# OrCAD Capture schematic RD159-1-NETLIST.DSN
size A3
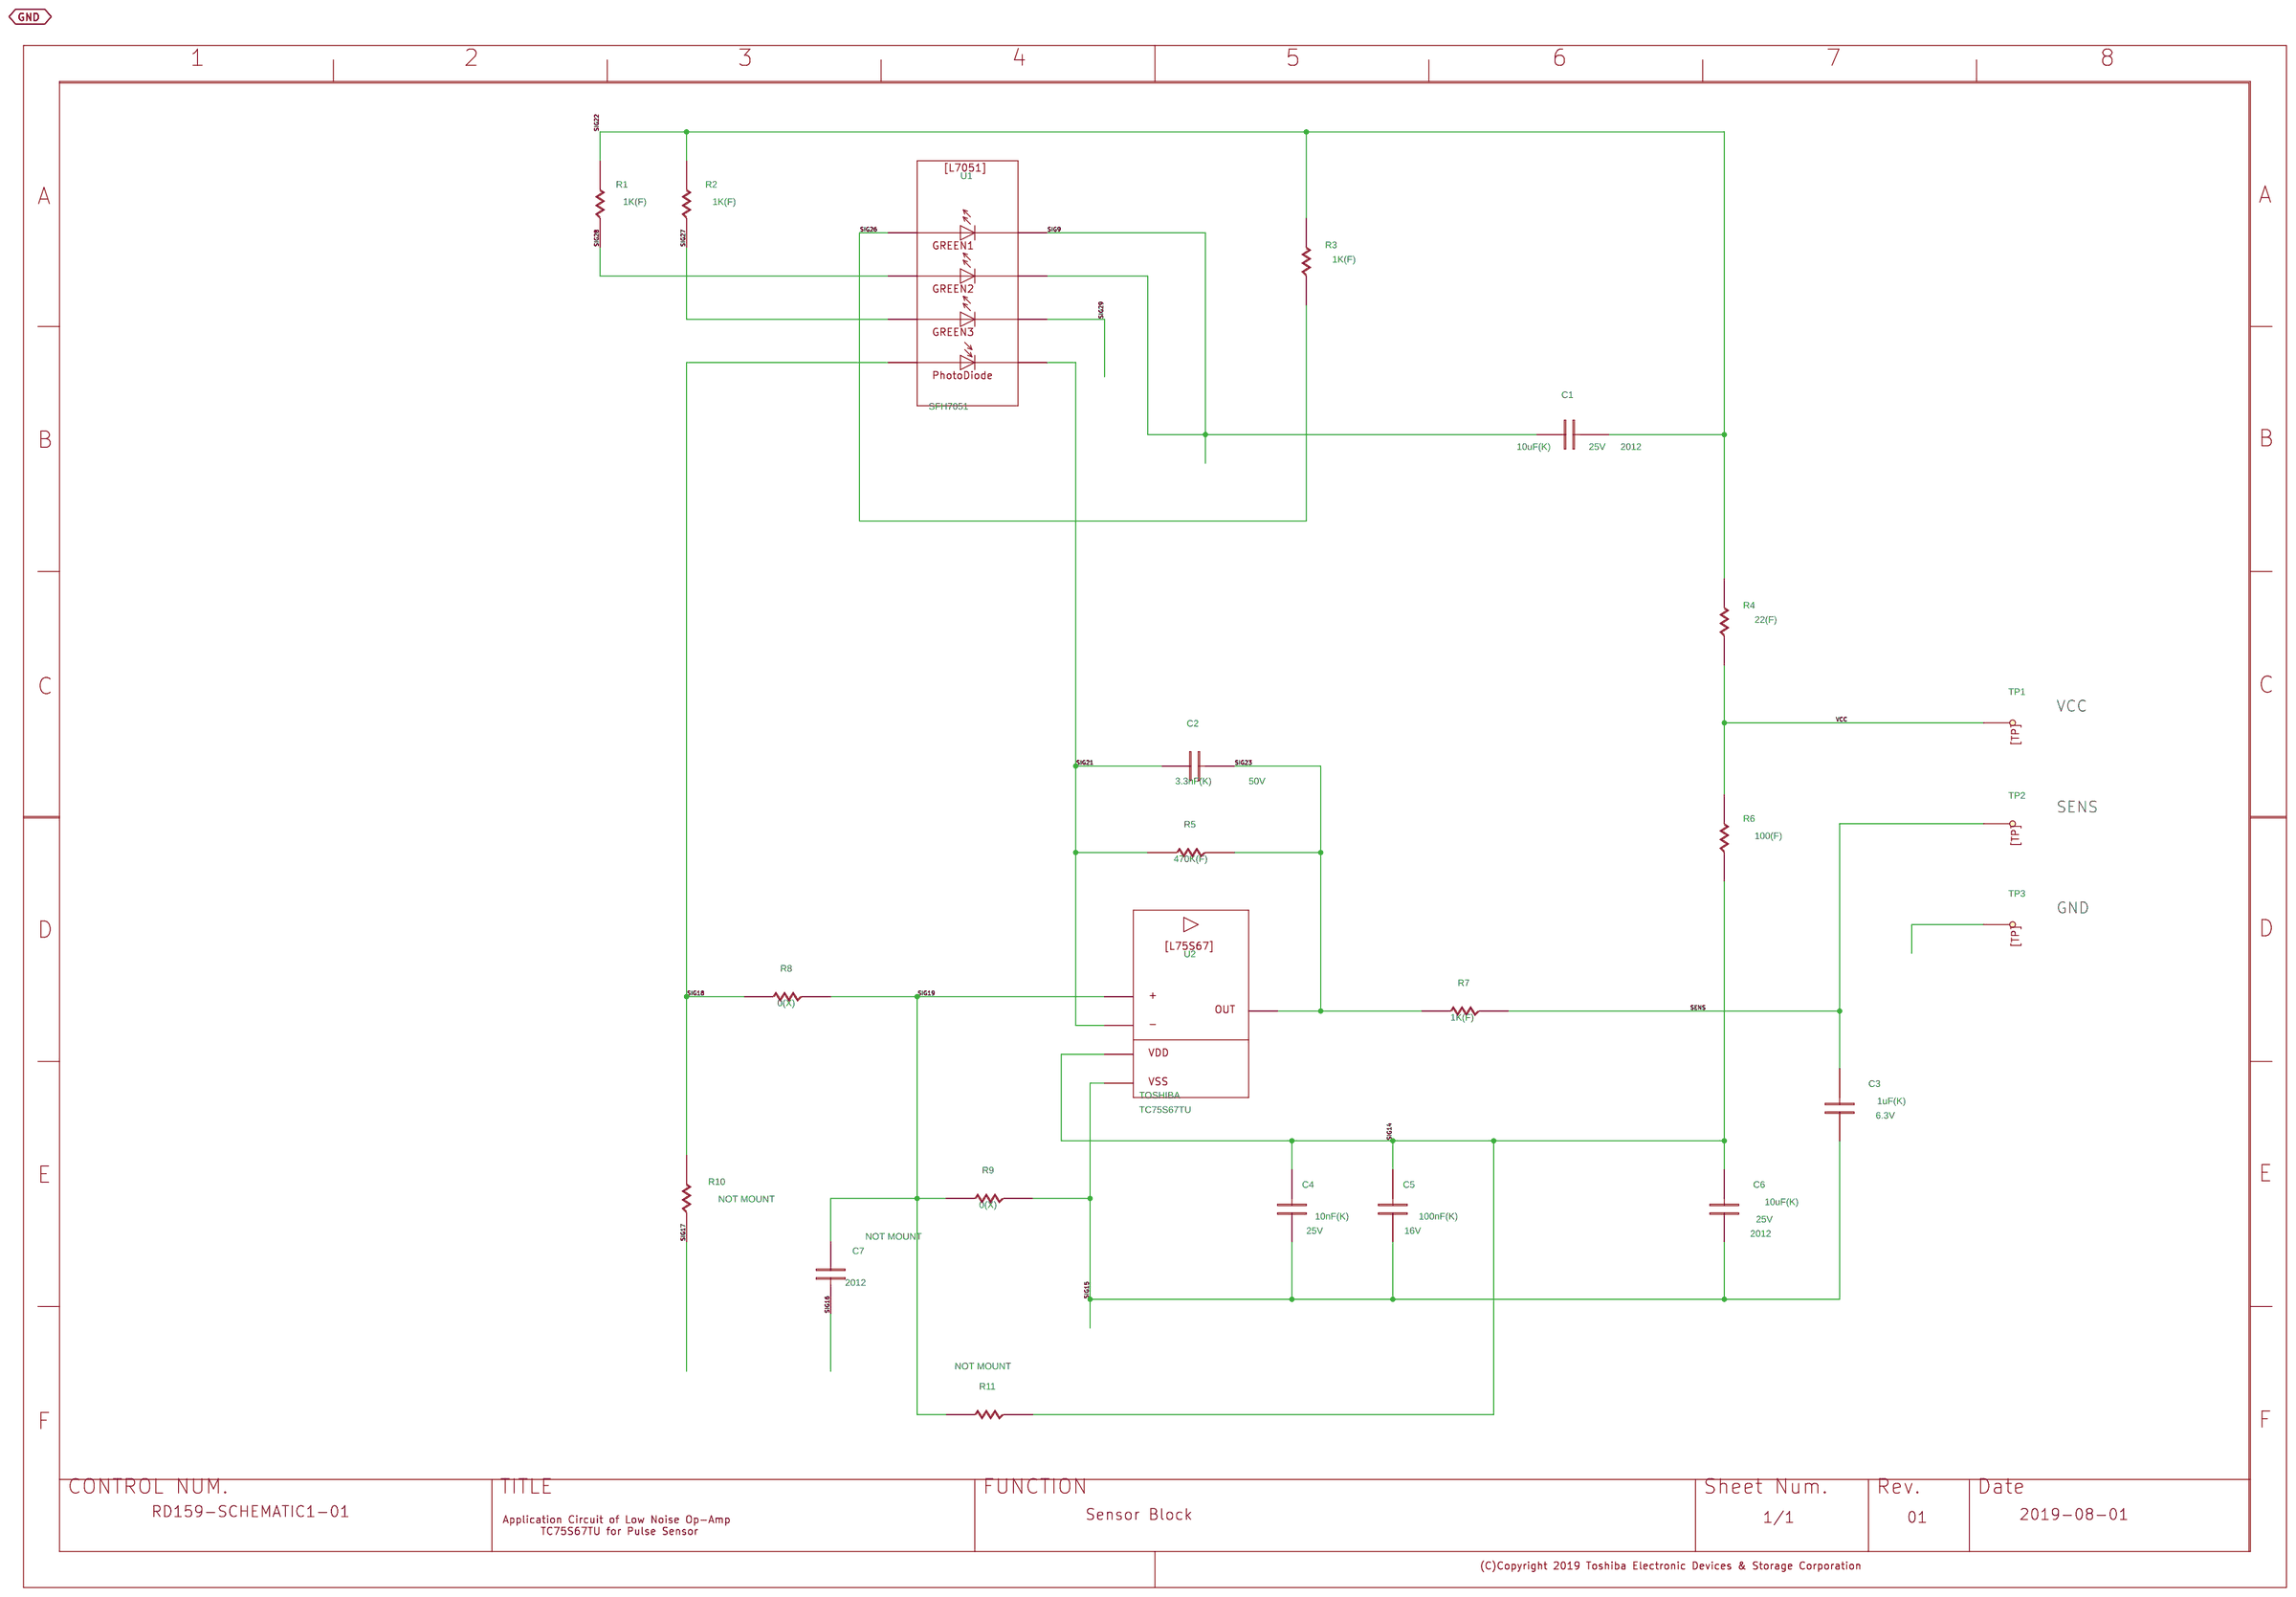
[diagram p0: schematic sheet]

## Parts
C1  C
C2  C
C3  C
C4  C
C5  C
C6  C
C7  C
R1  R
R2  R
R3  R
R4  R
R5  R
R6  R
R7  R
R8  R
R9  R
R10  R
R11  R
TP1  TP
TP2  TP
TP3  TP
U1  L7051
U2  L75S67
U?#1  WAKU_DEF100

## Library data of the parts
C1 C6 = C: CDBNAME: GDM030002136; COMPONENTNAME: GDM030002136_package; COMPONENTTYPE: 4; FUNCTION: GDM030002136; GCOUNT: 1; MAXGCOUNT: 1; PARTNAME: GDM030002136; SIZECODESMD: 2012; VAL1: 10uF(K); VAL2: 25V
C2 = C: CDBNAME: G36030133418; COMPONENTNAME: G36030133418_package; COMPONENTTYPE: 4; FUNCTION: G36030133418; GCOUNT: 1; MAXGCOUNT: 1; PARTNAME: G36030133418; SIZECODESMD: 1005; VAL1: 3.3nF(K); VAL2: 50V
C3 = C: CDBNAME: GDM030000207; COMPONENTNAME: GDM030000207_package; COMPONENTTYPE: 4; FUNCTION: GDM030000207; GCOUNT: 1; MAXGCOUNT: 1; PARTNAME: GDM030000207; SIZECODESMD: 1005; VAL1: 1uF(K); VAL2: 6.3V
C4 = C: CDBNAME: GDM030002097; COMPONENTNAME: GDM030002097_package; COMPONENTTYPE: 4; FUNCTION: GDM030002097; GCOUNT: 1; MAXGCOUNT: 1; PARTNAME: GDM030002097; SIZECODESMD: 1005; VAL1: 10nF(K); VAL2: 25V
C5 = C: CDBNAME: GDM030002515; COMPONENTNAME: GDM030002515_package; COMPONENTTYPE: 4; FUNCTION: GDM030002515; GCOUNT: 1; MAXGCOUNT: 1; PARTNAME: GDM030002515; SIZECODESMD: 1005; VAL1: 100nF(K); VAL2: 16V
C7 = C: CDBNAME: GDM030000019; COMPONENTNAME: GDM030000019_package; COMPONENTTYPE: 4; FUNCTION: GDM030000019; GCOUNT: 1; MAXGCOUNT: 1; NOTMOUNT: NOT MOUNT; PARTNAME: GDM030000019; SIZECODESMD: 2012
R1-R3 R7 = R: CDBNAME: GDM010001350; COMPONENTNAME: GDM010001350_package; COMPONENTTYPE: 4; FUNCTION: GDM010001350; GCOUNT: 1; MAXGCOUNT: 1; PARTNAME: GDM010001350; SIZECODESMD: 1005; VAL1: 1K(F); VAL2: 100mW
R4 = R: CDBNAME: GDM010003904; COMPONENTNAME: GDM010003904_package; COMPONENTTYPE: 4; FUNCTION: GDM010003904; GCOUNT: 1; MAXGCOUNT: 1; PARTNAME: GDM010003904; SIZECODESMD: 1005; VAL1: 22(F); VAL2: 100mW
R5 = R: CDBNAME: G36010118169; COMPONENTNAME: G36010118169_package; COMPONENTTYPE: 4; FUNCTION: G36010118169; GCOUNT: 1; MAXGCOUNT: 1; PARTNAME: G36010118169; SIZECODESMD: 1005; VAL1: 470K(F); VAL2: 100mW
R6 = R: CDBNAME: G36010118534; COMPONENTNAME: G36010118534_package; COMPONENTTYPE: 4; FUNCTION: G36010118534; GCOUNT: 1; MAXGCOUNT: 1; PARTNAME: G36010118534; SIZECODESMD: 1005; VAL1: 100(F); VAL2: 100mW
R8 R9 = R: CDBNAME: GDM010003025; COMPONENTNAME: GDM010003025_package; COMPONENTTYPE: 4; FUNCTION: GDM010003025; GCOUNT: 1; MAXGCOUNT: 1; PARTNAME: GDM010003025; SIZECODESMD: 1005; VAL1: 0(X); VAL2: 1A
R10 = R: CDBNAME: GDM010003025; COMPONENTNAME: GDM010003025_package; COMPONENTTYPE: 4; FUNCTION: GDM010003025; GCOUNT: 1; MAXGCOUNT: 1; NOTMOUNT: NOT MOUNT; PARTNAME: GDM010003025; SIZECODESMD: 1005
R11 = R: CDBNAME: GDM010002207; COMPONENTNAME: GDM010002207_package; COMPONENTTYPE: 4; FUNCTION: GDM010002207; GCOUNT: 1; MAXGCOUNT: 1; NOTMOUNT: NOT MOUNT; PARTNAME: GDM010002207; SIZECODESMD: 1005
TP1-TP3 = TP: CDBNAME: DCK7F1; COMPONENTNAME: DCK7F1_package; COMPONENTTYPE: 4; FUNCTION: DCK7F1; GCOUNT: 1; MAXGCOUNT: 1; PARTNAME: DCK7F1
U1 = L7051: CDBNAME: K47S002B; COMPONENTNAME: K47S002B_package; COMPONENTTYPE: 4; FUNCTION: K47S002B; GCOUNT: 1; MAXGCOUNT: 1; OUMEPARTTYPE: IC; PARTNAME: K47S002B; VAL1: SFH7051; VAL3: SFH7051
U2 = L75S67: CDBNAME: K47S002A; COMPONENTNAME: K47S002A_package; COMPONENTTYPE: 4; FUNCTION: K47S002A; GCOUNT: 1; MAXGCOUNT: 1; OUMEPARTTYPE: IC; PARTNAME: K47S002A; SAVEAREA0: -72307,-25685,103712,61936; UPDATEDATE: 2015/03/06; UPDATETIME: 13:02:06; UPDATEUSER: 19990028; USERCOMPTEXT3: TOSHIBA; VAL1: TC75S67TU; VAL3: TC75S67TU
U?#1 = WAKU_DEF100: COMPONENTTYPE: 2; DATE: 2019-08-01; DRAWINGNUMBER: RD159-SCHEMATIC1-01; FUNCTION: Sensor Block; REVISION: 01; SHEETNUMBER: 1/1; TITLE: Application Circuit of Low Noise Op-Amp / TC75S67TU for Pulse Sensor; UPDATEDATE: 2019/08/27; UPDATETIME: 13:18:10; UPDATEUSER: cae

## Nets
GND: C1.1 C3.1 C4.1 C5.1 C6.1 C7.2 R9.2 R10.2 TP3.1 U1.2 U1.3 U1.7 U2.2
VCC: R4.2 R6.1 TP1.1
SENS: C3.2 R7.2 TP2.1
SIG14: C4.2 C5.2 C6.2 R6.2 R11.2 U2.5
SIG18: R8.1 R10.1 U1.4
SIG19: C7.1 R8.2 R9.1 R11.1 U2.1
SIG21: C2.1 R5.1 U1.5 U2.3
SIG22: C1.2 R1.1 R2.1 R3.1 R4.1
SIG23: C2.2 R5.2 R7.1 U2.4
SIG26: R3.2 U1.1
SIG27: R2.2 U1.8
SIG28: R1.2 U1.6

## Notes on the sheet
- VCC
- SENS
- GND
